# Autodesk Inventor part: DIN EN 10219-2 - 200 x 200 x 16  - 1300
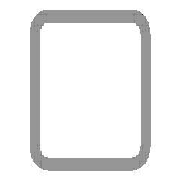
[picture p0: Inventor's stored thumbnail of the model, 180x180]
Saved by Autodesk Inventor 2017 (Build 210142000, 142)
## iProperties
Created: 2017-11
Part Number: DIN EN 10219-2 - 200 x 200 x 16  - 1300
Material: Steel, Mild
Description: Cold formed welded structural hollow sections of non-alloy and fine grain structural steel
Document SubType Name: Modeling
Standard: DIN
Designer: iusti
Standard Revision: 2006-07
Standards Organization: DIN
Language: en-US
Size Designation: 200 x 200 x 16
Categories: <MemberInstance><Categories><Category DisplayName="Structural Shapes" InternalName="089c4875-fa83-4c05-b084-43b9cc11f5ed" Mnemonic="GRDR"><CategoryParameter Dis
Stock Number: 200 x 200 x 16
Mass: 108961 g
Surface Area: 17564.1 cm^2
Volume: 13880.4 cm^3
Density: 7.85 g/cm^3
Appearance: Semi-Polished
_CCFamilyMember: 103
_CCFamilyDisplayName: DIN EN 10219-2 (Square Hollow Section - Cold Formed) - Cold formed welded structural hollow sections of non-alloy and fine grain structural steel
_FrameMemberDoc: Frame Member File
_Version: 15.0.0
_GetPNFromCC: 1
G_L: 1300.000 mm
G_W: 200.000 mm
G_H: 200.000 mm
+A865EAF7-CA2A-45A3-BC1A-64379BFC4A12+CUTDETAIL1: Cut
+34F438F3-E4A3-435A-9615-239FC3982D01+CUTDETAIL2: Cut
IsCustomPart: 1
Author: iusti
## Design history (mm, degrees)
node "Start plane"
node "End plane"
sketch "Sketch"
  geometry: L1 (-100, -52)-(-100, 52); L2 (-52, 100)-(52, 100); L3 (100, 52)-(100, -52); L4 (52, -100)-(-52, -100); L5 (-52, 84)-(52, 84); L6 (84, 52)-(84, -52); L7 (52, -84)-(-52, -84); L8 (-84, -52)-(-84, 52); L9 (0, 153.918)-(0, -153.918) reference; L10 (-153.918, 0)-(153.918, 0) reference; A1 r 48 centre (-52, -52) between (-100, -52) and (-52, -100); A2 r 48 centre (-52, 52) between (-52, 100) and (-100, 52); A3 r 48 centre (52, 52) between (100, 52) and (52, 100); A4 r 48 centre (52, -52) between (52, -100) and (100, -52); A5 r 32 centre (-52, 52) between (-52, 84) and (-84, 52); A6 r 32 centre (52, 52) between (84, 52) and (52, 84); A7 r 32 centre (52, -52) between (52, -84) and (84, -52); A8 r 32 centre (-52, -52) between (-84, -52) and (-52, -84)
  constraints: 16 end point, 16 point on circle, 8 centre point, 8 tangent, 4 parallel, 3 equal radius, 2 perpendicular, 7 other
  dimensions: "d7" = 48 radius of A1 (= G_IR); "d10" = 200 distance between parallel lines of L2 L4 (= G_H); "d11" = 200 distance between parallel lines of L1 L3 (= G_W); "d12" = 16 distance between parallel lines of L3 L6 (= G_T); "d15" = 100 distance between parallel lines of L2 L10 (= 0.5 x d10); "d16" = 100 distance between parallel lines of L9 L3 (= 0.5 x d11)
extrude "Body" new body sketch "Sketch" stored distance "d3" = 1300 (= G_L); taper "d4" = 0 deg
node "Driven Length"
  sketch "Sketch3"
    geometry: L1 (0, 0)-(10, 0) reference
    constraints: 2 end point, 1 horizontal
  workplane "Work Plane3"
  sketch "Sketch4"
    geometry: L1 (-2, 100)-(12, 100) reference; L2 (-2, 1400)-(12, 1400) reference
    dimensions: "d18" = 1300 distance between parallel lines of L1 L2 (derived)
workplane "Work Plane4"
split "Split1"
workplane "Work Plane5"
split "Split2"
body "Solid1"
other parameters: "G_W" = 200 [user parameter; used in 1 equation term], "G_H" = 200 [user parameter; used in 1 equation term], "G_T" = 16 [user parameter; used in 1 equation term], "G_IR" = 48 [user parameter; used in 1 equation term], "G_L" = 1300 (= d18) [user parameter; used in 1 equation term], "d17" = 90 deg
